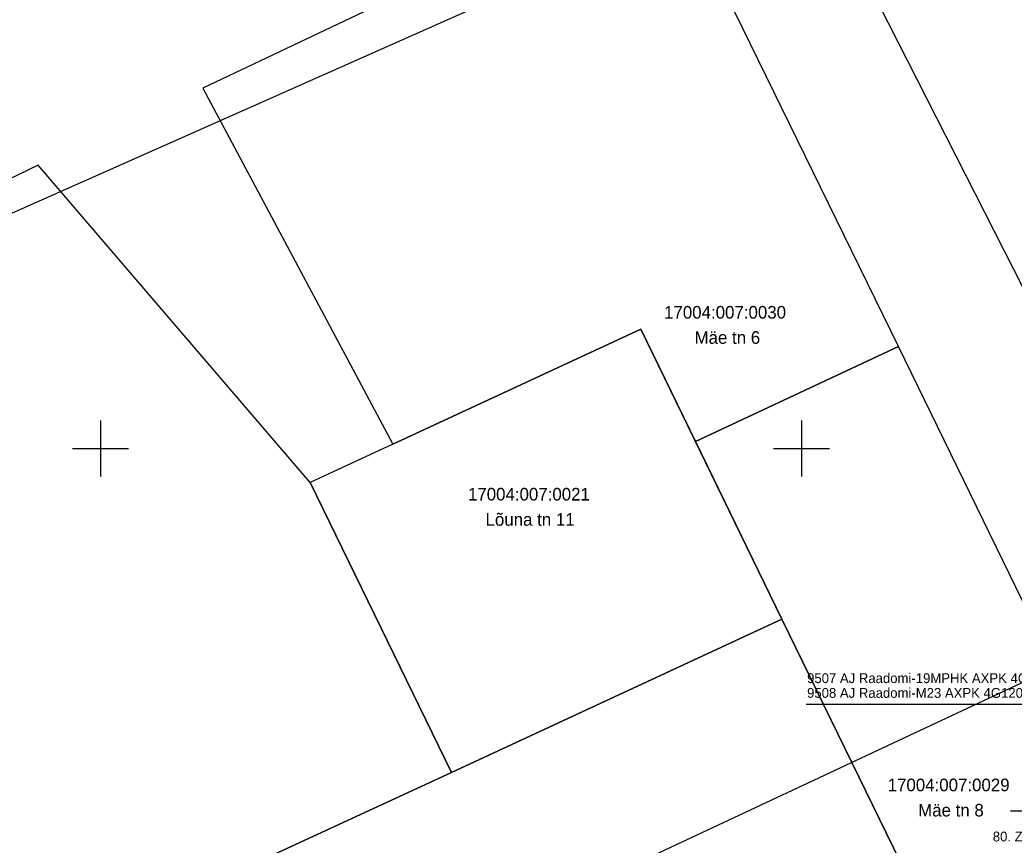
# Model space of a CAD drawing. Extents: x 642747 to 644424, y 6457048 to 6458238.
# Drawn here: x 643594.2 to 643665.2, y 6457521.7 to 6457580.6 of the extents above; entities that cross this region are included whole.
import ezdxf

# ---------------------------------------------------------------- set-up
doc = ezdxf.new("R2010")
doc.units = 0
for name, color, linetype in [('ABIJOONIS', 7, 'Continuous'), ('KOORDPUNKT', 7, 'Continuous'), ('MOOTPIIR', 7, 'Continuous'), ('PIIR', 7, 'Continuous'), ('VORK', 7, 'Continuous'), ('VORMISTUS', 7, 'Continuous')]:
    doc.layers.add(name, color=color, linetype=linetype)

msp = doc.modelspace()

# ---------------------------------------------------------------- linework, layer by layer
at = {"layer": 'ABIJOONIS'}
msp.add_lwpolyline([(643650.35, 6457531.767), (643671.561, 6457531.767), (643683.549, 6457521.797)], dxfattribs=at)
at = {"layer": 'KOORDPUNKT'}
msp.add_line((643664.909, 6457524.16), (643673.659, 6457524.16), dxfattribs=at)
at = {"layer": 'MOOTPIIR'}
msp.add_lwpolyline([(643525.446, 6457467.559), (643537.447, 6457435.458), (643944.848, 6457628.51), (644046.626, 6457529.09), (644067.022, 6457529.09), (644138.408, 6457598.401), (644075.1, 6457775.215), (644046.02, 6457752.582), (644092.466, 6457611.94), (644070.657, 6457576.375), (644041.981, 6457570.717), (643942.223, 6457662.862)], close=True, dxfattribs=at)
at = {"layer": 'PIIR'}
for points in [[(643807.33, 6457582.88), (643742.37, 6457711.12), (643680.23, 6457682.19), (643708.95, 6457623.53), (643648.6, 6457595.3), (643683.74, 6457526.24)], [(643656.93, 6457557.29), (643640.26, 6457591.36), (643607.29, 6457575.7), (643620.85, 6457550.31), (643638.54, 6457558.51), (643642.44, 6457550.51)], [(643584.66, 6457564.95), (643522.25, 6457534.76), (643549.02, 6457467.97), (643557.62, 6457471.91), (643559.88, 6457465.04), (643621.69, 6457493.88), (643604.64, 6457517.47), (643625.03, 6457526.9), (643614.96, 6457547.58), (643595.54, 6457570.21)], [(643625.03, 6457526.9), (643648.61, 6457537.83), (643638.54, 6457558.51), (643620.85, 6457550.31), (643614.96, 6457547.58)], [(643675.54, 6457519.09), (643656.93, 6457557.29), (643642.44, 6457550.51), (643648.61, 6457537.83), (643661.06, 6457512.31)], [(643621.69, 6457493.88), (643661.06, 6457512.31), (643648.61, 6457537.83), (643625.03, 6457526.9), (643604.64, 6457517.47)]]:
    msp.add_lwpolyline(points, close=True, dxfattribs=at)
at = {"layer": 'VORK'}
for p, q in [((643600, 6457552), (643600, 6457548)), ((643650, 6457552), (643650, 6457548)), ((643598, 6457550), (643602, 6457550)), ((643648, 6457550), (643652, 6457550))]:
    msp.add_line(p, q, dxfattribs=at)
at = {"layer": 'VORMISTUS'}
msp.add_line((643493.811, 6457522.44), (643911.466, 6457707.949), dxfattribs=at)

# ---------------------------------------------------------------- texts
at = {"layer": 'ABIJOONIS'}
for s, p in [('9507 AJ Raadomi-19MPHK AXPK 4G120 L=173.3m', (643650.407, 6457533.269)), ('9508 AJ Raadomi-M23 AXPK 4G120 L=22.7m', (643650.407, 6457532.218))]:
    msp.add_text(s, height=0.7, dxfattribs=at).set_placement(p)
at = {"layer": 'KOORDPUNKT'}
msp.add_text('80. Z=49.61 H=1.05', height=0.7, dxfattribs=at).set_placement((643663.655, 6457521.974))
at = {"layer": 'PIIR'}
for s, p in [('17004:007:0030', (643640.204, 6457559.27)), ('Mäe tn 6', (643642.378, 6457557.47)), ('17004:007:0021', (643626.211, 6457546.292)), ('Lõuna tn 11', (643627.466, 6457544.492)), ('17004:007:0029', (643656.156, 6457525.553)), ('Mäe tn 8', (643658.331, 6457523.753))]:
    msp.add_text(s, height=0.9, dxfattribs=at).set_placement(p)

doc.saveas('drawing.dxf')
